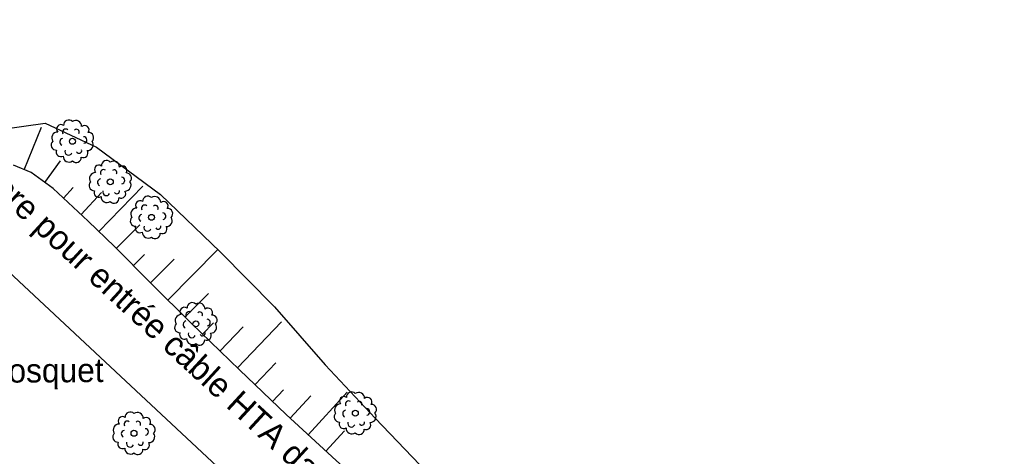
# Model space of a CAD drawing. Extents: x 343997 to 344255, y 298512 to 298767.
# Drawn here: x 344151.36 to 344191.53, y 298706.03 to 298723.99 of the extents above; entities that cross this region are included whole.
import ezdxf

# ---------------------------------------------------------------- set-up
doc = ezdxf.new("R2010")
doc.units = 0
for name, color, linetype in [('Commentaires', 7, 'Continuous'), ('Default', 7, 'Continuous'), ('DH_CADRE -CARTOUCHE', 7, 'Continuous'), ('DH_TEXTE', 7, 'Continuous'), ('PC_REBAR', 7, 'Continuous'), ('PS_OBJECT', 7, 'Continuous')]:
    doc.layers.add(name, color=color, linetype=linetype)

# ---------------------------------------------------------------- blocks, each defined once
blk = doc.blocks.new('ARB1')
at = {"layer": 'Default'}
blk.add_circle((0, 0), 0.0122, dxfattribs=at)
for centre, radius, start, end in [((-0.0153, 0.0664), 0.0211, 43.6925, 183.5969), ((0.0139, 0.0613), 0.0241, 358.4583, 125.1928), ((-0.0471, 0.0503), 0.0183, 53.9554, 222.2066), ((-0.0276, 0.037), 0.0134, 52.4396, 209.5496), ((0.0164, 0.038), 0.0112, 330.5895, 133.7127), ((0.0501, 0.0468), 0.0183, 325.1444, 131.0175), ((-0.0613, 0.0139), 0.0241, 88.4583, 215.1928), ((-0.0373, -0.0024), 0.0149, 103.7092, 242.3465), ((0.0458, 0.0052), 0.0137, 276.6214, 88.967), ((0.0613, -0.0139), 0.0241, 268.4583, 35.1928), ((0.0664, 0.0153), 0.0211, 313.6925, 93.5969), ((-0.0664, -0.0153), 0.0211, 133.6925, 273.5969), ((-0.0478, -0.0443), 0.019, 155.2243, 300.9377), ((-0.0163, -0.042), 0.0148, 159.5371, 338.1663), ((0.0271, -0.038), 0.0112, 210.5895, 13.7127), ((0.0448, -0.0483), 0.0188, 243.1323, 33.0297), ((-0.0139, -0.0613), 0.0241, 178.4583, 305.1928), ((0.0153, -0.0664), 0.0211, 223.6925, 3.5969)]:
    blk.add_arc(centre, radius, start, end, dxfattribs=at)

msp = doc.modelspace()

# ---------------------------------------------------------------- linework, layer by layer
at = {"layer": 'DH_CADRE -CARTOUCHE'}
msp.add_lwpolyline([(343997.309, 298660.673), (344147.183, 298520.807), (344245.09, 298625.72), (344095.215, 298765.586)], close=True, dxfattribs=at)
at = {"layer": 'PS_OBJECT'}
for p, q in [((344151.553, 298717.815), (344152.266, 298719.564)), ((344152.397, 298717.289), (344153.048, 298718.185)), ((344153.163, 298716.648), (344153.56, 298717.077)), ((344154.619, 298715.277), (344156.435, 298717.141)), ((344153.896, 298715.968), (344154.734, 298716.873)), ((344155.335, 298714.578), (344156.307, 298715.548)), ((344156.041, 298713.87), (344156.503, 298714.33)), ((344157.457, 298712.456), (344159.503, 298714.515)), ((344156.747, 298713.162), (344157.721, 298714.133)), ((344158.166, 298711.751), (344159.138, 298712.729)), ((344158.882, 298711.053), (344159.337, 298711.524)), ((344160.323, 298709.665), (344162.144, 298711.554)), ((344159.603, 298710.359), (344160.561, 298711.354)), ((344161.046, 298708.974), (344161.906, 298709.876)), ((344161.77, 298708.284), (344162.224, 298708.76)), ((344163.233, 298706.92), (344164.838, 298708.665)), ((344162.497, 298707.597), (344163.342, 298708.516)), ((344163.97, 298706.243), (344164.732, 298707.072))]:
    msp.add_line(p, q, dxfattribs=at)
for points in [[(344148.445, 298717.676), (344150.54, 298719.466), (344152.414, 298719.731), (344154.52, 298718.736), (344157.154, 298716.789), (344159.618, 298714.441), (344161.857, 298712.179), (344163.938, 298709.792), (344165.996, 298707.602), (344168.133, 298705.364), (344169.649, 298703.764), (344171.689, 298701.731), (344173.402, 298700.124), (344174.981, 298698.62), (344176.175, 298697.484), (344177.055, 298696.727), (344177.983, 298696.033), (344178.792, 298695.819), (344179.816, 298696.274), (344179.969, 298696.425)], [(344181.393, 298695.096), (344180.359, 298693.822), (344179.336, 298693.603), (344178.417, 298693.99), (344177.213, 298694.032), (344176.166, 298693.805), (344175.237, 298693.885), (344174.421, 298694.91), (344173.943, 298696.382), (344173.127, 298697.863), (344171.784, 298699.194), (344169.649, 298701.006), (344167.952, 298702.614), (344166.263, 298704.166), (344164.386, 298705.861), (344162.327, 298707.753), (344160.411, 298709.58), (344158.416, 298711.503), (344156.776, 298713.133), (344155.261, 298714.653), (344154.185, 298715.701), (344152.74, 298717.04), (344151.828, 298717.703), (344151.113, 298717.994)]]:
    msp.add_lwpolyline(points, dxfattribs=at)

# ---------------------------------------------------------------- block references
at = {"layer": 'PC_REBAR', "xscale": 10, "yscale": 10}
for p in [(344153.533, 298718.982), (344155.091, 298717.315), (344156.788, 298715.855), (344158.614, 298711.475), (344165.178, 298707.803), (344156.067, 298706.978)]:
    msp.add_blockref('ARB1', p, dxfattribs=at)

# ---------------------------------------------------------------- texts
at = {"layer": 'Commentaires'}
msp.add_text('Fausse chambre pour entrée câble HTA dans local technique', height=1.00027, rotation=317.3672, dxfattribs=at).set_placement((344144.279, 298722.385))
at = {"layer": 'DH_TEXTE'}
msp.add_text('Bosquet', height=0.9758, rotation=0.3665, dxfattribs=at).set_placement((344150.031, 298709.055))

doc.saveas('drawing.dxf')
